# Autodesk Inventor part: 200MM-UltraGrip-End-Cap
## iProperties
Created: 2012-04
Part Number: 200MM-UltraGrip-End-Cap
Document SubType Name: Modeling
Designer: D Cole
Density: 1 g/cm^3
Author: D Cole
